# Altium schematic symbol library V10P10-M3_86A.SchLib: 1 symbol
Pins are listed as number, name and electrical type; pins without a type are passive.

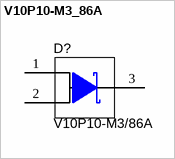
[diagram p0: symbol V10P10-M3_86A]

## V10P10-M3_86A
designator D?, comment V10P10-M3/86A
Diode, Schottky, 100 V, 10 A, TO-277A; Manufacturer: Vishay-Semiconductor; U/M: EA; Vf_V: 0.68; Value: 100V; Value1: 10A; Value2: 0.68V; Io_A: 10; Vr_V: 100; TJmax_C: 150; RJC_CperW: 3
signal-integrity model Diode
footprint TO-277A
footprint TO-277A WITH 4 RIGHT ROW VIAS (Vishay)
footprint TO-277A WITH 4 LEFT ROW VIAS (Vishay)
footprint TO-277A WITH VIAS (Vishay)
pins: 1 A, 2 A, 3 K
